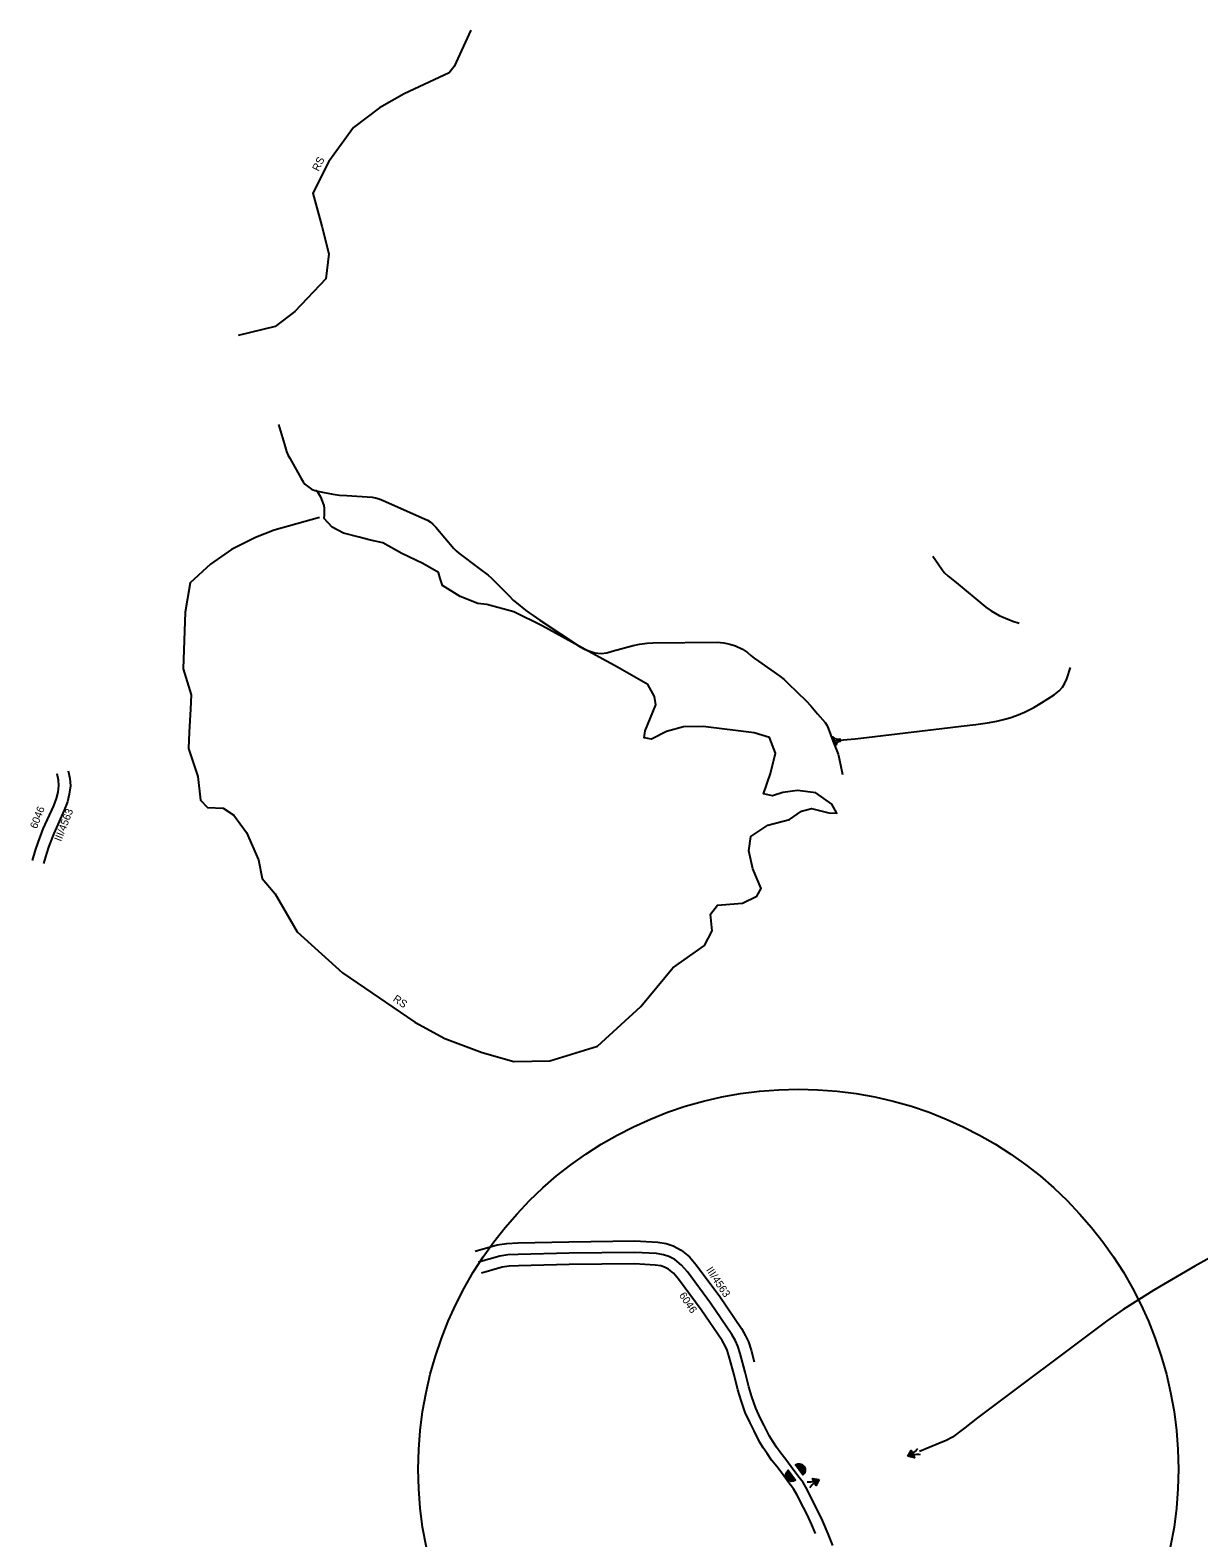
# Model space of a CAD drawing. Extents: x -546703 to -534152, y -1046534 to -1035676.
# Drawn here: x -543682 to -542145, y -1037660 to -1035676 of the extents above; entities that cross this region are included whole.
import ezdxf

# ---------------------------------------------------------------- set-up
doc = ezdxf.new("R2010")
doc.units = 0
for name, color, linetype in [('Vrstva 11', 7, 'Continuous'), ('Vrstva 17', 7, 'Continuous'), ('Vrstva 22', 7, 'Continuous'), ('Vrstva 23', 7, 'Continuous'), ('Vrstva 26', 7, 'Continuous'), ('Vrstva 37', 7, 'Continuous'), ('Vrstva 4', 7, 'Continuous')]:
    doc.layers.add(name, color=color, linetype=linetype)

msp = doc.modelspace()

# ---------------------------------------------------------------- linework, layer by layer
at = {"layer": 'Vrstva 11'}
for points in [[(-543355.6, -1036194.7), (-543347.7, -1036220.7), (-543345.1, -1036229.9), (-543343.2, -1036234.4), (-543340.8, -1036238.7), (-543325.9, -1036265.4), (-543323.3, -1036269.9), (-543320.8, -1036273), (-543317.4, -1036275.8), (-543312.3, -1036279.5), (-543307.8, -1036281.2), (-543302.3, -1036282.6), (-543284.1, -1036286), (-543275.3, -1036287.4), (-543265.8, -1036288.1), (-543232.5, -1036290.3), (-543227.8, -1036291.2), (-543223, -1036292.5), (-543218.1, -1036294.7), (-543159.4, -1036320.5), (-543155.9, -1036322.7), (-543152.4, -1036325.7), (-543148.7, -1036329.8), (-543124.9, -1036357.9), (-543121.9, -1036360.9), (-543118.5, -1036363.8), (-543091.4, -1036383.9), (-543079.6, -1036393), (-543075.9, -1036396.1), (-543072.3, -1036399.7), (-543053, -1036419.1), (-543046.4, -1036426), (-543042.3, -1036429.2), (-543030.8, -1036438.7), (-543025.8, -1036442.3), (-543020.4, -1036446), (-543011.9, -1036452), (-542958.6, -1036487.3), (-542952, -1036490.8), (-542946.1, -1036493), (-542939.3, -1036494.9), (-542931.2, -1036495.9), (-542923.8, -1036495.1), (-542916.7, -1036492.9), (-542889, -1036485.3), (-542880.5, -1036483.6), (-542870.8, -1036482.3), (-542863, -1036481.9), (-542778.3, -1036481.1), (-542769.9, -1036481.9), (-542762, -1036483.4), (-542754.2, -1036485.9), (-542745, -1036490.1), (-542738.8, -1036494.5), (-542734.4, -1036498.3), (-542729.6, -1036502.1), (-542724.2, -1036506), (-542695.9, -1036525.6), (-542690.4, -1036530), (-542685.1, -1036535.2), (-542661.6, -1036558), (-542655.4, -1036564.7), (-542646.5, -1036575.1), (-542636.3, -1036586.8), (-542634, -1036590.3), (-542632.3, -1036594.2), (-542626.1, -1036610.9), (-542619.3, -1036628.5), (-542618, -1036634.1), (-542613.5, -1036654.9)], [(-542494.6, -1036367.7), (-542483.1, -1036385.1), (-542479.7, -1036389.3), (-542474.8, -1036394.2), (-542463.9, -1036402.4), (-542425, -1036435.1), (-542418.2, -1036439.9), (-542407.7, -1036445.7), (-542399, -1036449.4), (-542389.4, -1036453.1), (-542381.2, -1036455.9)], [(-542626.1, -1036610.9), (-542607.4, -1036609.2), (-542597, -1036608.1), (-542589.4, -1036607.2), (-542482.8, -1036594.5), (-542457.3, -1036591.6), (-542438, -1036589.2), (-542422.9, -1036587.1), (-542410.6, -1036584.7), (-542401.6, -1036582.7), (-542393.4, -1036580.5), (-542384.7, -1036577.4), (-542374.2, -1036573), (-542362, -1036566.9), (-542351.7, -1036560.9), (-542335.2, -1036550.3), (-542328.5, -1036545), (-542324, -1036540.2), (-542321.1, -1036535.1), (-542318.6, -1036529.4), (-542313.5, -1036514.5)], [(-542111.5, -1037280.7), (-542149.9, -1037302.1), (-542204.2, -1037333.4), (-542244.4, -1037359.2), (-542266.4, -1037374.3), (-542435.8, -1037501.7), (-542452.8, -1037514.6), (-542468.7, -1037526.9), (-542477, -1037531.6), (-542486.8, -1037535.3), (-542512.5, -1037545.7)]]:
    msp.add_lwpolyline(points, dxfattribs=at)
msp.add_lwpolyline([(-542624.4, -1036610.3), (-542626.2, -1036605.4), (-542625.1, -1036606.7), (-542623.7, -1036607.5), (-542622, -1036608.1), (-542620.3, -1036608.4), (-542617.1, -1036608.3), (-542616.7, -1036611.8), (-542619.1, -1036612.2), (-542620.7, -1036613.1), (-542621.6, -1036614.2), (-542622.1, -1036616.4)], close=True, dxfattribs=at)
at = {"layer": 'Vrstva 17'}
for points in [[(-543632.5, -1036650.4), (-543630, -1036660.2), (-543629.3, -1036669.9), (-543630.8, -1036681), (-543633.2, -1036691.2), (-543637.5, -1036702.2), (-543651.1, -1036732.5), (-543657.7, -1036749.4), (-543660.8, -1036759), (-543664.7, -1036772.3)], [(-543096.8, -1037282.3), (-543067.8, -1037274.1), (-543055.3, -1037272), (-543040.7, -1037271.5), (-542973.6, -1037269.9), (-542886.6, -1037268.9), (-542856.6, -1037270.6), (-542845.7, -1037272.4), (-542836.3, -1037275.4), (-542825.9, -1037280.8), (-542815, -1037289.9), (-542806, -1037300.2), (-542775, -1037342.1), (-542746.3, -1037384), (-542741, -1037393.6), (-542737.4, -1037401.8), (-542733.8, -1037412.6), (-542729.8, -1037427.7)], [(-542649, -1037653.9), (-542653.9, -1037642.5), (-542659.8, -1037629.6), (-542664.9, -1037619.6), (-542673.1, -1037603.3), (-542677.9, -1037595.2), (-542684.2, -1037587.1), (-542693.1, -1037575), (-542700.2, -1037565.6), (-542706.8, -1037557.1), (-542712.7, -1037548.7), (-542717.9, -1037540.9), (-542722.7, -1037533), (-542729.9, -1037518.5), (-542735.2, -1037508), (-542741.5, -1037494.6), (-542747.1, -1037478.8), (-542751.3, -1037464.7), (-542756.2, -1037445.1), (-542762.6, -1037421.2), (-542765.5, -1037412.6), (-542768, -1037406.9), (-542771.9, -1037399.8), (-542799.5, -1037359.5), (-542829.4, -1037319), (-542836.1, -1037311.4), (-542842.6, -1037305.9), (-542847.8, -1037303.3), (-542852.8, -1037301.7), (-542859.9, -1037300.5), (-542887.3, -1037298.9), (-542973.1, -1037299.9), (-543039.9, -1037301.5), (-543052.2, -1037301.9), (-543061.2, -1037303.4), (-543088.7, -1037311.2)]]:
    msp.add_lwpolyline(points, dxfattribs=at)
at = {"layer": 'Vrstva 22'}
for points in [[(-543102.5, -1035675.7), (-543124.4, -1035723.3), (-543131.2, -1035731.9), (-543190.1, -1035759.4), (-543222.8, -1035777.7), (-543256.8, -1035803.9), (-543289.5, -1035848.3), (-543310.5, -1035890.2), (-543298.7, -1035933.4), (-543289.5, -1035970), (-543293.5, -1036002.7), (-543334, -1036045.9), (-543360.2, -1036065.5), (-543408.6, -1036077.3)], [(-543355.6, -1036194.7), (-543347.7, -1036220.7), (-543345.1, -1036229.9), (-543343.2, -1036234.4), (-543340.8, -1036238.7), (-543325.9, -1036265.4), (-543323.3, -1036269.9), (-543320.8, -1036273), (-543317.4, -1036275.8), (-543312.3, -1036279.5), (-543307.8, -1036281.2), (-543306.7, -1036281.5), (-543304.4, -1036283), (-543300.5, -1036289.8), (-543295.9, -1036301.2), (-543295.4, -1036305.1), (-543295.5, -1036313.8), (-543295.8, -1036317.7)], [(-543301.6, -1036317), (-543361.2, -1036333.4), (-543386, -1036343.2), (-543417.4, -1036358.9), (-543444.9, -1036378.5), (-543471.7, -1036402.7), (-543478.3, -1036441.3), (-543481.2, -1036516.2), (-543470.7, -1036550.2), (-543471.4, -1036569.2), (-543473.3, -1036599.3), (-543474, -1036620.9), (-543461.6, -1036657.5), (-543458.3, -1036688.9), (-543449.2, -1036698.7), (-543428.2, -1036699.4), (-543414.5, -1036708.5), (-543397.5, -1036731.4), (-543381.8, -1036767.4), (-543376.9, -1036791.9), (-543359.9, -1036812.2), (-543331.1, -1036861.9), (-543271.6, -1036916.2), (-543176.1, -1036981), (-543136.8, -1037002.6), (-543087.7, -1037020.9), (-543045.9, -1037032.7), (-542998.8, -1037032), (-542936, -1037012.4), (-542878.7, -1036960.4), (-542836.9, -1036909.3), (-542795, -1036879.9), (-542785.2, -1036861), (-542787.2, -1036838.7), (-542778, -1036826.9), (-542761.7, -1036825.6), (-542745.3, -1036824.3), (-542726.3, -1036815.2), (-542720.4, -1036805.3), (-542731.6, -1036779.2), (-542736.8, -1036755.6), (-542734.2, -1036736.7), (-542711.9, -1036721.6), (-542683.2, -1036714.4), (-542667.4, -1036703.3), (-542654.4, -1036700), (-542631.5, -1036705.3), (-542621, -1036705.9), (-542627.6, -1036694.1), (-542648.8, -1036679.4), (-542673, -1036676.2), (-542692, -1036678.8), (-542705.7, -1036683.3), (-542717.5, -1036680.7), (-542708.3, -1036653.9), (-542701.8, -1036627.1), (-542709.6, -1036606.2), (-542729.9, -1036600.3), (-542796.7, -1036591.8), (-542822.8, -1036592.4), (-542845.1, -1036598.3), (-542864.7, -1036608.8), (-542874.5, -1036606.8), (-542873.2, -1036597.7), (-542859.4, -1036563.6), (-542860.8, -1036552.5), (-542869.9, -1036536.8), (-542909.8, -1036513.9), (-542952, -1036490.8), (-543008.9, -1036459.3), (-543046.2, -1036441), (-543081.5, -1036431.2), (-543093.3, -1036429.9), (-543116.8, -1036420.7), (-543139.7, -1036406.3), (-543143, -1036397.2), (-543145, -1036389.3), (-543165.9, -1036377.5), (-543193.4, -1036364.5), (-543218.2, -1036350.1), (-543234.6, -1036346.8), (-543249.6, -1036342.9), (-543269.9, -1036337.6), (-543285, -1036329.8), (-543295.8, -1036317.7)], [(-543679.1, -1036768.1), (-543675.1, -1036754.6), (-543671.9, -1036744.4), (-543665, -1036726.7), (-543651.3, -1036696.4), (-543647.5, -1036686.7), (-543645.6, -1036678.3), (-543644.4, -1036669.5), (-543644.9, -1036662.5), (-543647, -1036654)], [(-542626.2, -1037669.7), (-542632.5, -1037654.3), (-542640.1, -1037636.5), (-542646.3, -1037623), (-542651.6, -1037612.8), (-542660, -1037596.1), (-542665.5, -1037586.8), (-542672.2, -1037578), (-542681.1, -1037566), (-542688.3, -1037556.5), (-542694.7, -1037548.2), (-542700.3, -1037540.2), (-542705.3, -1037532.8), (-542709.5, -1037525.8), (-542716.5, -1037511.7), (-542721.7, -1037501.5), (-542727.6, -1037488.9), (-542732.8, -1037474.1), (-542736.8, -1037460.7), (-542741.7, -1037441.4), (-542748.2, -1037416.9), (-542751.4, -1037407.2), (-542754.5, -1037400.2), (-542759.1, -1037391.9), (-542787.3, -1037350.8), (-542817.7, -1037309.6), (-542825.5, -1037300.6), (-542834.3, -1037293.4), (-542842.1, -1037289.3), (-542849.3, -1037287), (-542858.3, -1037285.5), (-542886.9, -1037283.9), (-542973.3, -1037284.9), (-543040.3, -1037286.5), (-543053.8, -1037286.9), (-543064.5, -1037288.8), (-543092.7, -1037296.7)]]:
    msp.add_lwpolyline(points, dxfattribs=at)
at = {"layer": 'Vrstva 23'}
for points in [[(-542686.6, -1037582), (-542688, -1037579.1), (-542688.1, -1037575.9), (-542687, -1037573), (-542684.9, -1037570.6), (-542675.3, -1037583.7), (-542678.2, -1037585.1), (-542681.3, -1037585.2), (-542684.3, -1037584.1)], [(-542686.1, -1037581.6), (-542687.4, -1037579), (-542687.5, -1037576), (-542686.5, -1037573.3), (-542684.9, -1037571.6), (-542676.2, -1037583.5), (-542678.3, -1037584.5), (-542681.2, -1037584.6), (-542684, -1037583.6)], [(-542685.6, -1037581.2), (-542686.8, -1037578.8), (-542686.9, -1037576.1), (-542686, -1037573.6), (-542685, -1037572.5), (-542677.1, -1037583.3), (-542678.5, -1037583.9), (-542681.1, -1037584), (-542683.7, -1037583.1)], [(-542685.1, -1037580.9), (-542686.2, -1037578.7), (-542686.3, -1037576.2), (-542685.4, -1037573.9), (-542685, -1037573.5), (-542678, -1037583), (-542678.6, -1037583.3), (-542681, -1037583.4), (-542683.3, -1037582.5)], [(-542684.6, -1037580.5), (-542685.6, -1037578.5), (-542685.7, -1037576.3), (-542685, -1037574.5), (-542679, -1037582.7), (-542680.9, -1037582.8), (-542683, -1037582)], [(-542684.1, -1037580.2), (-542685, -1037578.4), (-542685.1, -1037576.4), (-542684.8, -1037575.8), (-542680.2, -1037582.1), (-542680.9, -1037582.2), (-542682.7, -1037581.5)], [(-542683.7, -1037579.8), (-542684.4, -1037578.2), (-542684.4, -1037577.3), (-542681.6, -1037581.3), (-542682.4, -1037581)], [(-542664.3, -1037565.3), (-542662.9, -1037568.1), (-542662.8, -1037571.3), (-542663.8, -1037574.3), (-542666, -1037576.6), (-542675.6, -1037563.6), (-542672.8, -1037562.3), (-542669.6, -1037562.1), (-542666.6, -1037563.2)], [(-542664.8, -1037565.6), (-542663.5, -1037568.3), (-542663.4, -1037571.2), (-542664.4, -1037574), (-542665.9, -1037575.7), (-542674.7, -1037563.9), (-542672.6, -1037562.9), (-542669.7, -1037562.7), (-542667, -1037563.7)], [(-542665.3, -1037566), (-542664.1, -1037568.4), (-542664, -1037571.1), (-542664.9, -1037573.6), (-542665.9, -1037574.7), (-542673.8, -1037564.1), (-542672.5, -1037563.5), (-542669.8, -1037563.3), (-542667.3, -1037564.2)], [(-542665.8, -1037566.4), (-542664.7, -1037568.6), (-542664.6, -1037571), (-542665.4, -1037573.3), (-542665.8, -1037573.8), (-542672.9, -1037564.3), (-542672.3, -1037564), (-542669.9, -1037563.9), (-542667.6, -1037564.7)], [(-542666.3, -1037566.7), (-542665.3, -1037568.7), (-542665.2, -1037570.9), (-542665.8, -1037572.7), (-542671.9, -1037564.6), (-542670, -1037564.5), (-542667.9, -1037565.3)], [(-542666.7, -1037567.1), (-542665.9, -1037568.9), (-542665.8, -1037570.8), (-542666, -1037571.5), (-542670.7, -1037565.2), (-542670.1, -1037565.1), (-542668.2, -1037565.8)], [(-542667.2, -1037567.5), (-542666.5, -1037569), (-542666.5, -1037569.9), (-542669.4, -1037566), (-542668.5, -1037566.3)]]:
    msp.add_lwpolyline(points, close=True, dxfattribs=at)
at = {"layer": 'Vrstva 26'}
msp.add_circle((-542671.7, -1037569.2), 500, dxfattribs=at)
at = {"layer": 'Vrstva 37'}
for points in [[(-542527.6, -1037552.1), (-542523.1, -1037544.5), (-542518.9, -1037554.1)], [(-542525.4, -1037551.2), (-542523.3, -1037547.5), (-542521.3, -1037552.1)], [(-542523.9, -1037550.5), (-542523.4, -1037549.7), (-542522.9, -1037550.7)], [(-542644.3, -1037582.9), (-542648.4, -1037590.8), (-542653.1, -1037581.4)], [(-542646.4, -1037584), (-542648.4, -1037587.8), (-542650.6, -1037583.3)], [(-542647.9, -1037584.7), (-542648.4, -1037585.6), (-542648.9, -1037584.6)]]:
    msp.add_lwpolyline(points, close=True, dxfattribs=at)
for points in [[(-542521.5, -1037548), (-542519.5, -1037546.9), (-542517.7, -1037545.6), (-542516.1, -1037543.9), (-542514.7, -1037542.1)], [(-542520.4, -1037550.6), (-542518.3, -1037549.8), (-542516, -1037549.4), (-542513.7, -1037549.4), (-542511.4, -1037549.7)], [(-542651.4, -1037584.9), (-542653.5, -1037585.8), (-542655.7, -1037586.3), (-542658, -1037586.4), (-542660.3, -1037586.2)], [(-542650.1, -1037587.4), (-542652.1, -1037588.6), (-542653.9, -1037590), (-542655.4, -1037591.8), (-542656.6, -1037593.7)]]:
    msp.add_lwpolyline(points, dxfattribs=at)
at = {"layer": 'Vrstva 4'}
for points in [[(-543679.1, -1036768.1), (-543675.1, -1036754.6), (-543671.9, -1036744.4), (-543665, -1036726.7), (-543651.3, -1036696.4), (-543647.5, -1036686.7), (-543645.6, -1036678.3), (-543644.4, -1036669.5), (-543644.9, -1036662.5), (-543647, -1036654)], [(-542626.2, -1037669.7), (-542632.5, -1037654.3), (-542640.1, -1037636.5), (-542646.3, -1037623), (-542651.6, -1037612.8), (-542660, -1037596.1), (-542665.5, -1037586.8), (-542672.2, -1037578), (-542681.1, -1037566), (-542688.3, -1037556.5), (-542694.7, -1037548.2), (-542700.3, -1037540.2), (-542705.3, -1037532.8), (-542709.5, -1037525.8), (-542716.5, -1037511.7), (-542721.7, -1037501.5), (-542727.6, -1037488.9), (-542732.8, -1037474.1), (-542736.8, -1037460.7), (-542741.7, -1037441.4), (-542748.2, -1037416.9), (-542751.4, -1037407.2), (-542754.5, -1037400.2), (-542759.1, -1037391.9), (-542787.3, -1037350.8), (-542817.7, -1037309.6), (-542825.5, -1037300.6), (-542834.3, -1037293.4), (-542842.1, -1037289.3), (-542849.3, -1037287), (-542858.3, -1037285.5), (-542886.9, -1037283.9), (-542973.3, -1037284.9), (-543040.3, -1037286.5), (-543053.8, -1037286.9), (-543064.5, -1037288.8), (-543092.7, -1037296.7)]]:
    msp.add_lwpolyline(points, dxfattribs=at)

# ---------------------------------------------------------------- texts
at = {"layer": 'Vrstva 22'}
for s, rotation, p in [('RS', 63.6881, (-543302.9, -1035862.1)), ('6046', 68.7613, (-543673.7, -1036727.2)), ('RS', 325.4003, (-543205.9, -1036952.4)), ('6046', 303.8876, (-542829.1, -1037340.4))]:
    msp.add_text(s, height=10, rotation=rotation, dxfattribs=at).set_placement(p)
at = {"layer": 'Vrstva 4'}
for rotation, p in [(68.7613, (-543641.6, -1036744)), (303.8876, (-542793.6, -1037307))]:
    msp.add_text('III/4563', height=10, rotation=rotation, dxfattribs=at).set_placement(p)

doc.saveas('drawing.dxf')
